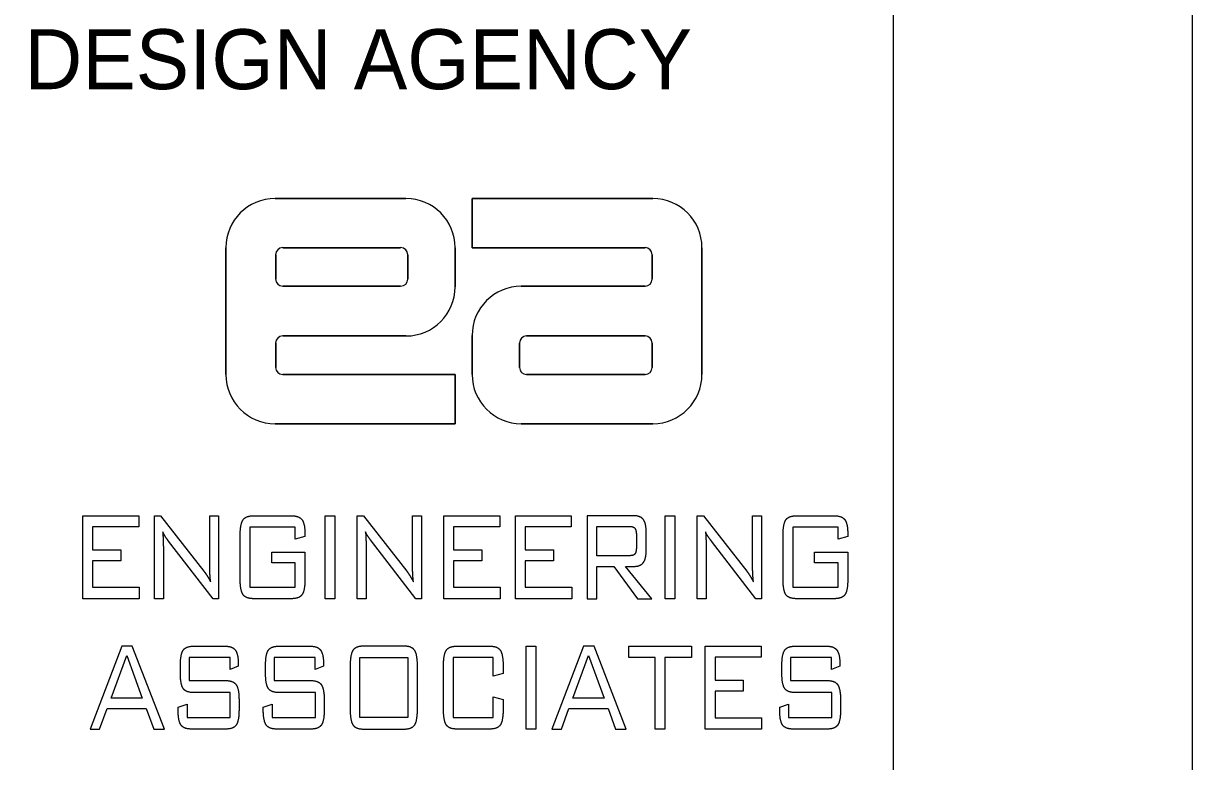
# Model space of a CAD drawing. Extents: x 0 to 34, y 0 to 22.
# Drawn here: x 32.048 to 34, y 3.728 to 4.96 of the extents above; entities that cross this region are included whole.
import ezdxf

# ---------------------------------------------------------------- set-up
doc = ezdxf.new("R2010")
doc.units = 0
for name, color, linetype in [('SH_Border', 7, 'Continuous'), ('SH_Cut_Line', 7, 'Continuous'), ('SH_Data', 7, 'Continuous'), ('TX_X_20', 7, 'Continuous')]:
    doc.layers.add(name, color=color, linetype=linetype)

msp = doc.modelspace()

# ---------------------------------------------------------------- linework, layer by layer
at = {"layer": 'SH_Border'}
msp.add_lwpolyline([(1.5, 21.5), (33.5, 21.5), (33.5, 0.5), (1.5, 0.5)], close=True, dxfattribs=at)
at = {"layer": 'SH_Cut_Line'}
msp.add_lwpolyline([(0, 0), (34, 0), (34, 22), (0, 22)], close=True, dxfattribs=at)
at = {"layer": 'SH_Data'}
msp.add_line((32.75, 4), (32.75, 4), dxfattribs=at)
at = {"layer": 'TX_X_20'}
for p, q in [((32.6869, 4.6677), (32.4684, 4.6677)), ((32.4684, 4.6677), (32.6869, 4.6677)), ((32.7974, 4.6677), (33.0989, 4.6677)), ((32.7974, 4.5856), (32.7974, 4.6677)), ((32.3863, 4.5856), (32.3863, 4.3741)), ((32.3863, 4.3741), (32.3863, 4.5856)), ((32.4694, 4.5332), (32.4694, 4.5738)), ((32.4694, 4.5738), (32.4694, 4.5332)), ((32.4812, 4.5856), (32.678, 4.5856)), ((32.678, 4.5856), (32.4812, 4.5856)), ((32.6898, 4.5738), (32.6898, 4.5332)), ((32.6898, 4.5332), (32.6898, 4.5738)), ((32.7689, 4.5204), (32.7689, 4.5856)), ((32.7689, 4.5856), (32.7689, 4.5204)), ((33.086, 4.5856), (32.7974, 4.5856)), ((33.0979, 4.5738), (33.0979, 4.5332)), ((33.0979, 4.5332), (33.0979, 4.5738)), ((33.1809, 4.3741), (33.1809, 4.5856)), ((33.1809, 4.5856), (33.1809, 4.3741)), ((32.678, 4.5214), (32.4812, 4.5214)), ((32.4812, 4.5214), (32.678, 4.5214)), ((33.086, 4.5214), (32.8794, 4.5214)), ((32.8794, 4.5214), (33.086, 4.5214)), ((32.4812, 4.4383), (32.6869, 4.4383)), ((32.6869, 4.4383), (32.4812, 4.4383)), ((32.7974, 4.4393), (32.7974, 4.3741)), ((32.7974, 4.3741), (32.7974, 4.4393)), ((32.8883, 4.4383), (33.086, 4.4383)), ((33.086, 4.4383), (32.8883, 4.4383)), ((32.4694, 4.3859), (32.4694, 4.4265)), ((32.4694, 4.4265), (32.4694, 4.3859)), ((32.8765, 4.3859), (32.8765, 4.4265)), ((32.8765, 4.4265), (32.8765, 4.3859)), ((33.0979, 4.4265), (33.0979, 4.3859)), ((33.0979, 4.3859), (33.0979, 4.4265)), ((32.4812, 4.3741), (32.7689, 4.3741)), ((32.7689, 4.3741), (32.7689, 4.292)), ((33.086, 4.3741), (32.8883, 4.3741)), ((32.8883, 4.3741), (33.086, 4.3741)), ((32.7689, 4.292), (32.4684, 4.292)), ((32.8794, 4.292), (33.0989, 4.292)), ((33.0989, 4.292), (32.8794, 4.292)), ((32.4329, 4.1384), (32.4956, 4.1384)), ((33.339, 4.1384), (33.4017, 4.1384)), ((32.4101, 4.0328), (32.4101, 4.1057)), ((33.0715, 4.1062), (33.0715, 4.086)), ((33.0879, 4.0806), (33.0879, 4.1116)), ((33.3163, 4.0328), (33.3163, 4.1057)), ((32.4956, 4), (32.4329, 4)), ((33.4017, 4), (33.339, 4)), ((32.3328, 3.9209), (32.3843, 3.9209)), ((32.475, 3.9209), (32.5265, 3.9209)), ((32.6834, 3.9209), (32.6165, 3.9209)), ((32.7722, 3.9209), (32.8264, 3.9209)), ((33.3369, 3.9209), (33.3884, 3.9209)), ((32.3103, 3.8761), (32.3103, 3.8882)), ((32.4525, 3.8761), (32.4525, 3.8882)), ((32.5937, 3.8882), (32.5937, 3.8152)), ((32.706, 3.8152), (32.706, 3.8882)), ((32.7495, 3.8152), (32.7495, 3.8882)), ((33.3144, 3.8761), (33.3144, 3.8882)), ((32.4082, 3.8308), (32.4082, 3.8152)), ((32.5504, 3.8308), (32.5504, 3.8152)), ((33.4123, 3.8308), (33.4123, 3.8152)), ((32.3857, 3.7825), (32.3293, 3.7825)), ((32.5279, 3.7825), (32.4715, 3.7825)), ((32.6165, 3.7825), (32.6834, 3.7825)), ((32.8264, 3.7825), (32.7722, 3.7825)), ((33.3898, 3.7825), (33.3334, 3.7825))]:
    msp.add_line(p, q, dxfattribs=at)
for points in [[(33.0989, 4.6677), (32.7974, 4.6677), (32.7974, 4.5856), (33.086, 4.5856)], [(32.4684, 4.292), (32.7689, 4.292), (32.7689, 4.3741), (32.4812, 4.3741)], [(32.2819, 4.0816), (32.2819, 4), (32.2671, 4), (32.2671, 4.1384), (32.2773, 4.1384), (32.3497, 4.0458)], [(32.3593, 4.0625), (32.3593, 4.1384), (32.3741, 4.1384), (32.3741, 4), (32.365, 4), (32.2906, 4.0962)], [(32.6204, 4.0816), (32.6204, 4), (32.6056, 4), (32.6056, 4.1384), (32.6158, 4.1384), (32.6883, 4.0458)], [(32.6978, 4.0625), (32.6978, 4.1384), (32.7126, 4.1384), (32.7126, 4), (32.7035, 4), (32.6291, 4.0962)], [(33.0674, 4.1384), (32.9893, 4.1384), (32.9893, 4), (33.0056, 4), (33.0056, 4.0539), (33.034, 4.0539), (33.0734, 4), (33.0974, 4), (33.0532, 4.0539), (33.0674, 4.0539)], [(33.188, 4.0816), (33.188, 4), (33.1732, 4), (33.1732, 4.1384), (33.1834, 4.1384), (33.2559, 4.0458)], [(33.2654, 4.0625), (33.2654, 4.1384), (33.2802, 4.1384), (33.2802, 4), (33.2711, 4), (33.1967, 4.0962)], [(32.5183, 4.1072), (32.5183, 4.1038), (32.5022, 4.0992), (32.5022, 4.1196), (32.4263, 4.1196), (32.4263, 4.0192), (32.5022, 4.0192), (32.5022, 4.0599), (32.463, 4.0599), (32.463, 4.0775), (32.5183, 4.0775), (32.5183, 4.0328)], [(33.061, 4.0718), (33.0056, 4.0718), (33.0056, 4.1205), (33.061, 4.1205)], [(33.4244, 4.1072), (33.4244, 4.1038), (33.4083, 4.0992), (33.4083, 4.1196), (33.3324, 4.1196), (33.3324, 4.0192), (33.4083, 4.0192), (33.4083, 4.0599), (33.3691, 4.0599), (33.3691, 4.0775), (33.4244, 4.0775), (33.4244, 4.0328)], [(32.407, 3.8905), (32.407, 3.8877), (32.3932, 3.882), (32.3932, 3.9021), (32.3248, 3.9021), (32.3248, 3.8635), (32.3857, 3.8635)], [(32.5493, 3.8905), (32.5493, 3.8877), (32.5354, 3.882), (32.5354, 3.9021), (32.467, 3.9021), (32.467, 3.8635), (32.5279, 3.8635)], [(32.849, 3.8882), (32.849, 3.8751), (32.8327, 3.8708), (32.8327, 3.9021), (32.7656, 3.9021), (32.7656, 3.8018), (32.8327, 3.8018), (32.8327, 3.8364), (32.849, 3.8316), (32.849, 3.8152)], [(33.4112, 3.8905), (33.4112, 3.8877), (33.3973, 3.882), (33.3973, 3.9021), (33.3289, 3.9021), (33.3289, 3.8635), (33.3898, 3.8635)], [(32.3065, 3.8152), (32.3065, 3.819), (32.3215, 3.824), (32.3215, 3.8018), (32.3937, 3.8018), (32.3937, 3.8434), (32.3328, 3.8434)], [(32.4487, 3.8152), (32.4487, 3.819), (32.4637, 3.824), (32.4637, 3.8018), (32.5359, 3.8018), (32.5359, 3.8434), (32.475, 3.8434)], [(33.3107, 3.8152), (33.3107, 3.819), (33.3257, 3.824), (33.3257, 3.8018), (33.3978, 3.8018), (33.3978, 3.8434), (33.3369, 3.8434)]]:
    msp.add_lwpolyline(points, dxfattribs=at)
for points in [[(32.1474, 4), (32.1474, 4.1384), (32.2407, 4.1384), (32.2407, 4.1198), (32.1637, 4.1198), (32.1637, 4.0813), (32.2108, 4.0813), (32.2108, 4.0631), (32.1637, 4.0631), (32.1637, 4.019), (32.2414, 4.019), (32.2414, 4)], [(32.552, 4), (32.552, 4.1384), (32.5682, 4.1384), (32.5682, 4)], [(32.75, 4), (32.75, 4.1384), (32.8433, 4.1384), (32.8433, 4.1198), (32.7662, 4.1198), (32.7662, 4.0813), (32.8133, 4.0813), (32.8133, 4.0631), (32.7662, 4.0631), (32.7662, 4.019), (32.844, 4.019), (32.844, 4)], [(32.8697, 4), (32.8697, 4.1384), (32.9629, 4.1384), (32.9629, 4.1198), (32.8859, 4.1198), (32.8859, 4.0813), (32.933, 4.0813), (32.933, 4.0631), (32.8859, 4.0631), (32.8859, 4.019), (32.9637, 4.019), (32.9637, 4)], [(33.1196, 4), (33.1196, 4.1384), (33.1358, 4.1384), (33.1358, 4)], [(32.1595, 3.7825), (32.1755, 3.7825), (32.1879, 3.8166), (32.2534, 3.8166), (32.2658, 3.7825), (32.2836, 3.7825), (32.2297, 3.9209), (32.2124, 3.9209)], [(32.1946, 3.8342), (32.2207, 3.9051), (32.2468, 3.8342)], [(32.8873, 3.7825), (32.8873, 3.9209), (32.9036, 3.9209), (32.9036, 3.7825)], [(32.9305, 3.7825), (32.9465, 3.7825), (32.9589, 3.8166), (33.0244, 3.8166), (33.0368, 3.7825), (33.0546, 3.7825), (33.0008, 3.9209), (32.9834, 3.9209)], [(32.9657, 3.8342), (32.9917, 3.9051), (33.0178, 3.8342)], [(33.1192, 3.9021), (33.1192, 3.7825), (33.103, 3.7825), (33.103, 3.9021), (33.0588, 3.9021), (33.0588, 3.9209), (33.1636, 3.9209), (33.1636, 3.9021)], [(33.1866, 3.7825), (33.1866, 3.9209), (33.2798, 3.9209), (33.2798, 3.9024), (33.2028, 3.9024), (33.2028, 3.8639), (33.2499, 3.8639), (33.2499, 3.8456), (33.2028, 3.8456), (33.2028, 3.8015), (33.2806, 3.8015), (33.2806, 3.7825)], [(32.6099, 3.8018), (32.6099, 3.9021), (32.69, 3.9021), (32.69, 3.8018)]]:
    msp.add_lwpolyline(points, close=True, dxfattribs=at)
for centre, radius, start, end in [((32.4684, 4.5856), 0.0821, 90, 180), ((32.4684, 4.5856), 0.0821, 90, 180), ((32.6869, 4.5856), 0.0821, 0, 90), ((32.6869, 4.5856), 0.0821, 0, 90), ((33.0989, 4.5856), 0.0821, 0, 90), ((33.0989, 4.5856), 0.0821, 0, 90), ((32.4812, 4.5738), 0.0119, 90, 180), ((32.4812, 4.5738), 0.0119, 90, 180), ((32.678, 4.5738), 0.0119, 0, 90), ((32.678, 4.5738), 0.0119, 0, 90), ((33.086, 4.5738), 0.0119, 0, 90), ((33.086, 4.5738), 0.0119, 0, 90), ((32.4812, 4.5332), 0.0119, 180, 270), ((32.4812, 4.5332), 0.0119, 180, 270), ((32.678, 4.5332), 0.0119, 270, 0), ((32.678, 4.5332), 0.0119, 270, 0), ((33.086, 4.5332), 0.0119, 270, 0), ((33.086, 4.5332), 0.0119, 270, 0), ((32.6869, 4.5204), 0.0821, 270, 360), ((32.6869, 4.5204), 0.0821, 270, 360), ((32.8794, 4.4393), 0.0821, 90, 180), ((32.8794, 4.4393), 0.0821, 90, 180), ((32.4812, 4.4265), 0.0119, 90, 180), ((32.4812, 4.4265), 0.0119, 90, 180), ((32.8883, 4.4265), 0.0119, 90, 180), ((32.8883, 4.4265), 0.0119, 90, 180), ((33.086, 4.4265), 0.0119, 0, 90), ((33.086, 4.4265), 0.0119, 0, 90), ((32.4684, 4.3741), 0.0821, 180, 270), ((32.4684, 4.3741), 0.0821, 180, 270), ((32.4812, 4.3859), 0.0119, 180, 270), ((32.4812, 4.3859), 0.0119, 180, 270), ((32.8794, 4.3741), 0.0821, 180, 270), ((32.8794, 4.3741), 0.0821, 180, 270), ((32.8883, 4.3859), 0.0119, 180, 270), ((32.8883, 4.3859), 0.0119, 180, 270), ((33.086, 4.3859), 0.0119, 270, 0), ((33.086, 4.3859), 0.0119, 270, 0), ((33.0989, 4.3741), 0.0821, 270, 360), ((33.0989, 4.3741), 0.0821, 270, 360)]:
    msp.add_arc(centre, radius, start, end, dxfattribs=at)
for points in [[(32.4149, 4.1315), (32.4196, 4.1384), (32.4329, 4.1384)], [(32.4956, 4.1384), (32.5086, 4.1384), (32.5134, 4.1317)], [(33.0831, 4.1321), (33.0783, 4.1384), (33.0674, 4.1384)], [(33.321, 4.1315), (33.3257, 4.1384), (33.339, 4.1384)], [(33.4017, 4.1384), (33.4147, 4.1384), (33.4196, 4.1317)], [(32.4101, 4.1057), (32.4101, 4.1245), (32.4149, 4.1315)], [(32.5134, 4.1317), (32.5183, 4.1249), (32.5183, 4.1072)], [(33.061, 4.1205), (33.067, 4.1205), (33.0692, 4.1173)], [(33.0879, 4.1116), (33.0879, 4.1257), (33.0831, 4.1321)], [(33.3163, 4.1057), (33.3163, 4.1245), (33.321, 4.1315)], [(33.4196, 4.1317), (33.4244, 4.1249), (33.4244, 4.1072)], [(32.2889, 4.0983), (32.2834, 4.1054), (32.2808, 4.1118)], [(32.2808, 4.1118), (32.2813, 4.1055), (32.2816, 4.0984)], [(32.6275, 4.0983), (32.622, 4.1054), (32.6193, 4.1118)], [(32.6193, 4.1118), (32.6199, 4.1055), (32.6201, 4.0984)], [(33.0692, 4.1173), (33.0715, 4.1141), (33.0715, 4.1062)], [(33.1951, 4.0983), (33.1896, 4.1054), (33.1869, 4.1118)], [(33.1869, 4.1118), (33.1875, 4.1055), (33.1877, 4.0984)], [(32.2816, 4.0984), (32.2819, 4.0913), (32.2819, 4.0816)], [(32.2906, 4.0962), (32.29, 4.0969), (32.2889, 4.0983)], [(32.6201, 4.0984), (32.6204, 4.0913), (32.6204, 4.0816)], [(32.6291, 4.0962), (32.6286, 4.0969), (32.6275, 4.0983)], [(33.0715, 4.086), (33.0715, 4.0781), (33.0693, 4.0749)], [(33.0831, 4.0603), (33.0879, 4.0666), (33.0879, 4.0806)], [(33.1877, 4.0984), (33.188, 4.0913), (33.188, 4.0816)], [(33.1967, 4.0962), (33.1962, 4.0969), (33.1951, 4.0983)], [(32.3596, 4.0424), (32.3593, 4.0496), (32.3593, 4.0625)], [(32.6982, 4.0424), (32.6978, 4.0496), (32.6978, 4.0625)], [(33.0693, 4.0749), (33.0671, 4.0718), (33.061, 4.0718)], [(33.0674, 4.0539), (33.0783, 4.0539), (33.0831, 4.0603)], [(33.2658, 4.0424), (33.2654, 4.0496), (33.2654, 4.0625)], [(32.3497, 4.0458), (32.3522, 4.0427), (32.355, 4.0382)], [(32.3607, 4.0284), (32.36, 4.0351), (32.3596, 4.0424)], [(32.6883, 4.0458), (32.6907, 4.0427), (32.6935, 4.0382)], [(32.6993, 4.0284), (32.6985, 4.0351), (32.6982, 4.0424)], [(33.2559, 4.0458), (33.2583, 4.0427), (33.2611, 4.0382)], [(33.2669, 4.0284), (33.2661, 4.0351), (33.2658, 4.0424)], [(32.355, 4.0382), (32.3578, 4.0338), (32.3607, 4.0284)], [(32.4149, 4.0069), (32.4101, 4.0139), (32.4101, 4.0328)], [(32.5183, 4.0328), (32.5183, 4.0138), (32.5135, 4.0069)], [(32.6935, 4.0382), (32.6963, 4.0338), (32.6993, 4.0284)], [(33.2611, 4.0382), (33.2639, 4.0338), (33.2669, 4.0284)], [(33.321, 4.0069), (33.3163, 4.0139), (33.3163, 4.0328)], [(33.4244, 4.0328), (33.4244, 4.0138), (33.4197, 4.0069)], [(32.4329, 4), (32.4196, 4), (32.4149, 4.0069)], [(32.5135, 4.0069), (32.5088, 4), (32.4956, 4)], [(33.339, 4), (33.3257, 4), (33.321, 4.0069)], [(33.4197, 4.0069), (33.4149, 4), (33.4017, 4)], [(32.3103, 3.8882), (32.3103, 3.9072), (32.3149, 3.914)], [(32.3149, 3.914), (32.3196, 3.9209), (32.3328, 3.9209)], [(32.3843, 3.9209), (32.3972, 3.9209), (32.4021, 3.9142)], [(32.4021, 3.9142), (32.407, 3.9074), (32.407, 3.8905)], [(32.4525, 3.8882), (32.4525, 3.9072), (32.4571, 3.914)], [(32.4571, 3.914), (32.4618, 3.9209), (32.475, 3.9209)], [(32.5265, 3.9209), (32.5394, 3.9209), (32.5443, 3.9142)], [(32.5443, 3.9142), (32.5493, 3.9074), (32.5493, 3.8905)], [(32.5984, 3.914), (32.5937, 3.907), (32.5937, 3.8882)], [(32.6165, 3.9209), (32.6032, 3.9209), (32.5984, 3.914)], [(32.7013, 3.914), (32.6965, 3.9209), (32.6834, 3.9209)], [(32.706, 3.8882), (32.706, 3.9072), (32.7013, 3.914)], [(32.7495, 3.8882), (32.7495, 3.9072), (32.7543, 3.914)], [(32.7543, 3.914), (32.759, 3.9209), (32.7722, 3.9209)], [(32.8264, 3.9209), (32.8396, 3.9209), (32.8443, 3.9141)], [(32.8443, 3.9141), (32.849, 3.9073), (32.849, 3.8882)], [(33.3144, 3.8882), (33.3144, 3.9072), (33.3191, 3.914)], [(33.3191, 3.914), (33.3237, 3.9209), (33.3369, 3.9209)], [(33.3884, 3.9209), (33.4014, 3.9209), (33.4063, 3.9142)], [(33.4063, 3.9142), (33.4112, 3.9074), (33.4112, 3.8905)], [(32.3149, 3.8503), (32.3103, 3.8571), (32.3103, 3.8761)], [(32.4571, 3.8503), (32.4525, 3.8571), (32.4525, 3.8761)], [(33.3191, 3.8503), (33.3144, 3.8571), (33.3144, 3.8761)], [(32.3328, 3.8434), (32.3196, 3.8434), (32.3149, 3.8503)], [(32.3857, 3.8635), (32.3986, 3.8635), (32.4034, 3.8566)], [(32.4034, 3.8566), (32.4082, 3.8498), (32.4082, 3.8308)], [(32.475, 3.8434), (32.4618, 3.8434), (32.4571, 3.8503)], [(32.5279, 3.8635), (32.5408, 3.8635), (32.5456, 3.8566)], [(32.5456, 3.8566), (32.5504, 3.8498), (32.5504, 3.8308)], [(33.3369, 3.8434), (33.3237, 3.8434), (33.3191, 3.8503)], [(33.3898, 3.8635), (33.4028, 3.8635), (33.4075, 3.8566)], [(33.4075, 3.8566), (33.4123, 3.8498), (33.4123, 3.8308)], [(32.3113, 3.7894), (32.3065, 3.7963), (32.3065, 3.8152)], [(32.4082, 3.8152), (32.4082, 3.7961), (32.4035, 3.7893)], [(32.4535, 3.7894), (32.4487, 3.7963), (32.4487, 3.8152)], [(32.5504, 3.8152), (32.5504, 3.7961), (32.5457, 3.7893)], [(32.5937, 3.8152), (32.5937, 3.7964), (32.5984, 3.7895)], [(32.7013, 3.7893), (32.706, 3.7961), (32.706, 3.8152)], [(32.7543, 3.7894), (32.7495, 3.7963), (32.7495, 3.8152)], [(32.849, 3.8152), (32.849, 3.7961), (32.8443, 3.7893)], [(33.3154, 3.7894), (33.3107, 3.7963), (33.3107, 3.8152)], [(33.4123, 3.8152), (33.4123, 3.7961), (33.4076, 3.7893)], [(32.3293, 3.7825), (32.3161, 3.7825), (32.3113, 3.7894)], [(32.4035, 3.7893), (32.3988, 3.7825), (32.3857, 3.7825)], [(32.4715, 3.7825), (32.4583, 3.7825), (32.4535, 3.7894)], [(32.5457, 3.7893), (32.541, 3.7825), (32.5279, 3.7825)], [(32.5984, 3.7895), (32.6032, 3.7825), (32.6165, 3.7825)], [(32.6834, 3.7825), (32.6965, 3.7825), (32.7013, 3.7893)], [(32.7722, 3.7825), (32.759, 3.7825), (32.7543, 3.7894)], [(32.8443, 3.7893), (32.8396, 3.7825), (32.8264, 3.7825)], [(33.3334, 3.7825), (33.3202, 3.7825), (33.3154, 3.7894)], [(33.4076, 3.7893), (33.4029, 3.7825), (33.3898, 3.7825)]]:
    msp.add_open_spline(points, degree=2, dxfattribs=at)

# ---------------------------------------------------------------- texts
at = {"layer": 'SH_Data'}
msp.add_text('DESIGN AGENCY', height=0.1, dxfattribs=at).set_placement((32.05, 4.85))

doc.saveas('drawing.dxf')
